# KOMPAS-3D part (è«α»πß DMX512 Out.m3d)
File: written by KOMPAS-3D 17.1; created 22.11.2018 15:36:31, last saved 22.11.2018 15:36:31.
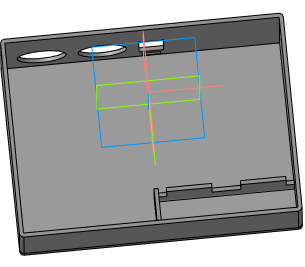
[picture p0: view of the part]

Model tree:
1. Эскиз:2
2. Элемент выдавливания:1
     Толщина стенки 2 = 2; Расстояние 1 = 55
3. Скругление:1
     Радиус = 2
4. Эскиз:3
5. Элемент выдавливания:2
     Расстояние 2 = 137.2
6. Эскиз:4
7. Элемент выдавливания:3
     Толщина стенки 2 = 2; Расстояние 2 = 137.2
8. Скругление:2
     Радиус = 2
9. Скругление:3
     Радиус = 2
10. Эскиз:5
11. Элемент выдавливания:4
     Расстояние 2 = 2
12. Эскиз:8
13. Элемент выдавливания:5
     Толщина стенки 1 = 2; Расстояние 2 = 68
14. Эскиз:9
15. Элемент выдавливания:6
     Толщина стенки 1 = 2; Расстояние 2 = 21
16. Эскиз:10
17. Элемент выдавливания:7
     Расстояние 2 = 10
18. Эскиз:11
19. Элемент выдавливания:8
     Расстояние 2 = 10
20. Эскиз:12
21. Элемент выдавливания:9
     Расстояние 2 = 3

Referenced files in E:\SIM DMX\Тест DMX 512 Out\3D принтер\: Сборка 2.a3d
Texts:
  крышка 2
